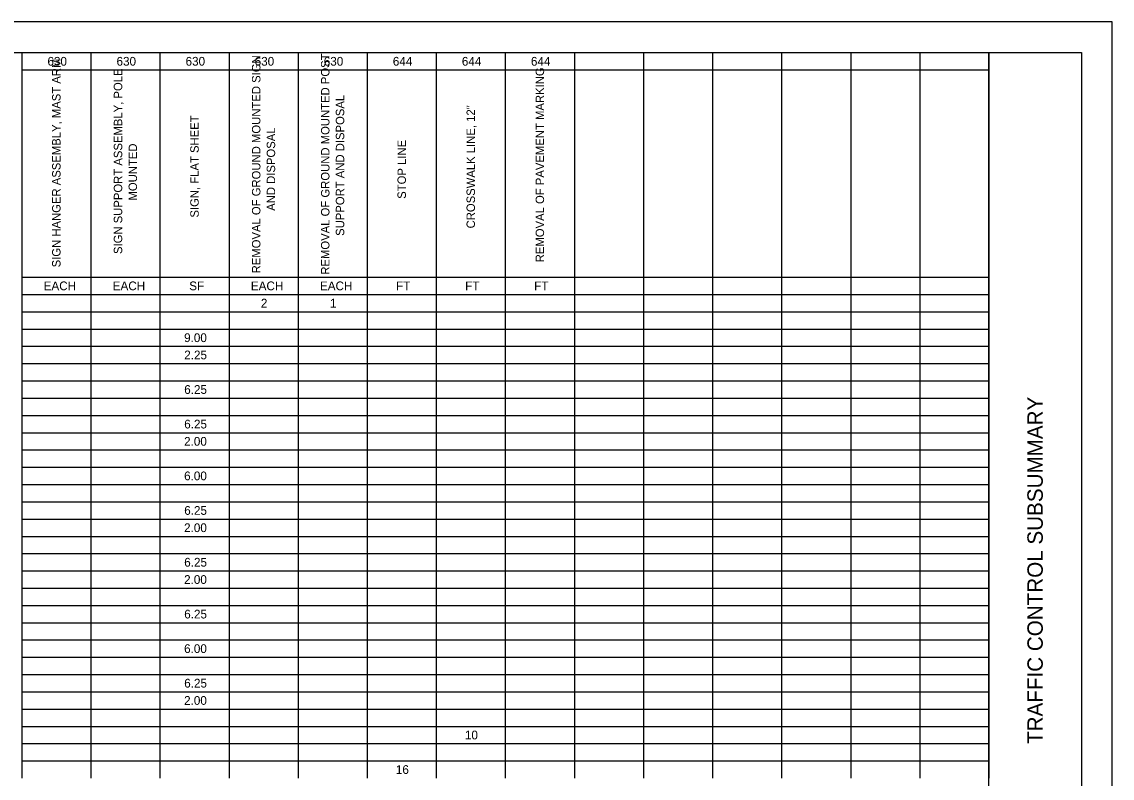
# Model space of a CAD drawing. Extents: x 0 to 34, y 0 to 22.
# Drawn here: x 16.33 to 34, y 9.74 to 22 of the extents above; entities that cross this region are included whole.
import ezdxf

# ---------------------------------------------------------------- set-up
doc = ezdxf.new("R2010")
doc.units = 0
for name, color, linetype in [('SH_Border', 7, 'Continuous'), ('SH_Cut_Line', 7, 'Continuous'), ('SH_Data', 7, 'Continuous')]:
    doc.layers.add(name, color=color, linetype=linetype)

msp = doc.modelspace()

# ---------------------------------------------------------------- linework, layer by layer
at = {"layer": 'SH_Border'}
msp.add_line((32, 0.5), (32, 21.5), dxfattribs=at)
msp.add_lwpolyline([(1.5, 21.5), (33.5, 21.5), (33.5, 0.5), (1.5, 0.5)], close=True, dxfattribs=at)
at = {"layer": 'SH_Cut_Line'}
msp.add_lwpolyline([(0, 0), (34, 0), (34, 22), (0, 22)], close=True, dxfattribs=at)
at = {"layer": 'SH_Data'}
for p, q in [((16.325, 21.5), (24.163, 21.5)), ((16.325, 21.5), (16.325, 21.22)), ((17.445, 21.5), (17.445, 21.22)), ((18.565, 21.5), (18.565, 21.22)), ((19.684, 21.5), (19.684, 21.22)), ((20.804, 21.5), (20.804, 21.22)), ((21.923, 21.5), (21.923, 21.22)), ((23.043, 21.5), (23.043, 21.22)), ((24.163, 21.5), (25.282, 21.5)), ((24.163, 21.5), (24.163, 21.22)), ((25.282, 21.5), (27.522, 21.5)), ((25.282, 21.5), (25.282, 21.22)), ((26.402, 21.5), (26.402, 21.22)), ((27.522, 21.5), (30.88, 21.5)), ((27.522, 21.5), (27.522, 21.22)), ((28.641, 21.5), (28.641, 21.22)), ((29.761, 21.5), (29.761, 21.22)), ((30.88, 21.5), (32, 21.5)), ((30.88, 21.5), (30.88, 21.22)), ((32, 21.5), (32, 21.22)), ((16.325, 21.22), (24.163, 21.22)), ((16.325, 21.22), (16.325, 20.94)), ((17.445, 21.22), (17.445, 20.94)), ((18.565, 21.22), (18.565, 20.94)), ((19.684, 21.22), (19.684, 20.94)), ((20.804, 21.22), (20.804, 20.94)), ((21.923, 21.22), (21.923, 20.94)), ((23.043, 21.22), (23.043, 20.94)), ((24.163, 21.22), (25.282, 21.22)), ((24.163, 21.22), (24.163, 20.94)), ((25.282, 21.22), (27.522, 21.22)), ((25.282, 21.22), (25.282, 20.94)), ((26.402, 21.22), (26.402, 20.94)), ((27.522, 21.22), (30.88, 21.22)), ((27.522, 21.22), (27.522, 20.94)), ((28.641, 21.22), (28.641, 20.94)), ((29.761, 21.22), (29.761, 20.94)), ((30.88, 21.22), (32, 21.22)), ((30.88, 21.22), (30.88, 20.94)), ((32, 21.22), (32, 20.94)), ((16.325, 20.94), (16.325, 20.66)), ((17.445, 20.94), (17.445, 20.66)), ((18.565, 20.94), (18.565, 20.66)), ((19.684, 20.94), (19.684, 20.66)), ((20.804, 20.94), (20.804, 20.66)), ((21.923, 20.94), (21.923, 20.66)), ((23.043, 20.94), (23.043, 20.66)), ((24.163, 20.94), (24.163, 20.66)), ((25.282, 20.94), (25.282, 20.66)), ((26.402, 20.94), (26.402, 20.66)), ((27.522, 20.94), (27.522, 20.66)), ((28.641, 20.94), (28.641, 20.66)), ((29.761, 20.94), (29.761, 20.66)), ((30.88, 20.94), (30.88, 20.66)), ((32, 20.94), (32, 20.66)), ((16.325, 20.66), (16.325, 20.38)), ((17.445, 20.66), (17.445, 20.38)), ((18.565, 20.66), (18.565, 20.38)), ((19.684, 20.66), (19.684, 20.38)), ((20.804, 20.66), (20.804, 20.38)), ((21.923, 20.66), (21.923, 20.38)), ((23.043, 20.66), (23.043, 20.38)), ((24.163, 20.66), (24.163, 20.38)), ((25.282, 20.66), (25.282, 20.38)), ((26.402, 20.66), (26.402, 20.38)), ((27.522, 20.66), (27.522, 20.38)), ((28.641, 20.66), (28.641, 20.38)), ((29.761, 20.66), (29.761, 20.38)), ((30.88, 20.66), (30.88, 20.38)), ((32, 20.66), (32, 20.38)), ((16.325, 20.38), (16.325, 20.1)), ((17.445, 20.38), (17.445, 20.1)), ((18.565, 20.38), (18.565, 20.1)), ((19.684, 20.38), (19.684, 20.1)), ((20.804, 20.38), (20.804, 20.1)), ((21.923, 20.38), (21.923, 20.1)), ((23.043, 20.38), (23.043, 20.1)), ((24.163, 20.38), (24.163, 20.1)), ((25.282, 20.38), (25.282, 20.1)), ((26.402, 20.38), (26.402, 20.1)), ((27.522, 20.38), (27.522, 20.1)), ((28.641, 20.38), (28.641, 20.1)), ((29.761, 20.38), (29.761, 20.1)), ((30.88, 20.38), (30.88, 20.1)), ((32, 20.38), (32, 20.1)), ((16.325, 20.1), (16.325, 19.82)), ((17.445, 20.1), (17.445, 19.82)), ((18.565, 20.1), (18.565, 19.82)), ((19.684, 20.1), (19.684, 19.82)), ((20.804, 20.1), (20.804, 19.82)), ((21.923, 20.1), (21.923, 19.82)), ((23.043, 20.1), (23.043, 19.82)), ((24.163, 20.1), (24.163, 19.82)), ((25.282, 20.1), (25.282, 19.82)), ((26.402, 20.1), (26.402, 19.82)), ((27.522, 20.1), (27.522, 19.82)), ((28.641, 20.1), (28.641, 19.82)), ((29.761, 20.1), (29.761, 19.82)), ((30.88, 20.1), (30.88, 19.82)), ((32, 20.1), (32, 19.82)), ((16.325, 19.82), (16.325, 19.54)), ((17.445, 19.82), (17.445, 19.54)), ((18.565, 19.82), (18.565, 19.54)), ((19.684, 19.82), (19.684, 19.54)), ((20.804, 19.82), (20.804, 19.54)), ((21.923, 19.82), (21.923, 19.54)), ((23.043, 19.82), (23.043, 19.54)), ((24.163, 19.82), (24.163, 19.54)), ((25.282, 19.82), (25.282, 19.54)), ((26.402, 19.82), (26.402, 19.54)), ((27.522, 19.82), (27.522, 19.54)), ((28.641, 19.82), (28.641, 19.54)), ((29.761, 19.82), (29.761, 19.54)), ((30.88, 19.82), (30.88, 19.54)), ((32, 19.82), (32, 19.54)), ((16.325, 19.54), (16.325, 18.98)), ((17.445, 19.54), (17.445, 18.98)), ((18.565, 19.54), (18.565, 18.98)), ((19.684, 19.54), (19.684, 18.98)), ((20.804, 19.54), (20.804, 18.98)), ((21.923, 19.54), (21.923, 18.98)), ((23.043, 19.54), (23.043, 18.98)), ((24.163, 19.54), (24.163, 18.98)), ((25.282, 19.54), (25.282, 18.98)), ((26.402, 19.54), (26.402, 18.98)), ((27.522, 19.54), (27.522, 18.98)), ((28.641, 19.54), (28.641, 18.98)), ((29.761, 19.54), (29.761, 18.98)), ((30.88, 19.54), (30.88, 18.98)), ((32, 19.54), (32, 18.98)), ((16.325, 18.98), (16.325, 18.14)), ((17.445, 18.98), (17.445, 18.14)), ((18.565, 18.98), (18.565, 18.14)), ((19.684, 18.98), (19.684, 18.14)), ((20.804, 18.98), (20.804, 18.14)), ((21.923, 18.98), (21.923, 18.14)), ((23.043, 18.98), (23.043, 18.14)), ((24.163, 18.98), (24.163, 18.14)), ((25.282, 18.98), (25.282, 18.14)), ((26.402, 18.98), (26.402, 18.14)), ((27.522, 18.98), (27.522, 18.14)), ((28.641, 18.98), (28.641, 18.14)), ((29.761, 18.98), (29.761, 18.14)), ((30.88, 18.98), (30.88, 18.14)), ((32, 18.98), (32, 18.14)), ((16.325, 18.14), (16.325, 17.86)), ((17.445, 18.14), (17.445, 17.86)), ((18.565, 18.14), (18.565, 17.86)), ((19.684, 18.14), (19.684, 17.86)), ((20.804, 18.14), (20.804, 17.86)), ((21.923, 18.14), (21.923, 17.86)), ((23.043, 18.14), (23.043, 17.86)), ((24.163, 18.14), (24.163, 17.86)), ((25.282, 18.14), (25.282, 17.86)), ((26.402, 18.14), (26.402, 17.86)), ((27.522, 18.14), (27.522, 17.86)), ((28.641, 18.14), (28.641, 17.86)), ((29.761, 18.14), (29.761, 17.86)), ((30.88, 18.14), (30.88, 17.86)), ((32, 18.14), (32, 17.86)), ((16.325, 17.86), (24.163, 17.86)), ((16.325, 17.86), (16.325, 17.3)), ((17.445, 17.86), (17.445, 17.3)), ((18.565, 17.86), (18.565, 17.3)), ((19.684, 17.86), (19.684, 17.3)), ((20.804, 17.86), (20.804, 17.3)), ((21.923, 17.86), (21.923, 17.3)), ((23.043, 17.86), (23.043, 17.3)), ((24.163, 17.86), (25.282, 17.86)), ((24.163, 17.86), (24.163, 17.3)), ((25.282, 17.86), (27.522, 17.86)), ((25.282, 17.86), (25.282, 17.3)), ((26.402, 17.86), (26.402, 17.3)), ((27.522, 17.86), (30.88, 17.86)), ((27.522, 17.86), (27.522, 17.3)), ((28.641, 17.86), (28.641, 17.3)), ((29.761, 17.86), (29.761, 17.3)), ((30.88, 17.86), (32, 17.86)), ((30.88, 17.86), (30.88, 17.3)), ((32, 17.86), (32, 17.3)), ((16.325, 17.58), (24.163, 17.58)), ((24.163, 17.58), (25.282, 17.58)), ((25.282, 17.58), (27.522, 17.58)), ((27.522, 17.58), (30.88, 17.58)), ((30.88, 17.58), (32, 17.58)), ((16.325, 17.3), (24.163, 17.3)), ((16.325, 17.3), (16.325, 17.02)), ((17.445, 17.3), (17.445, 17.02)), ((18.565, 17.3), (18.565, 17.02)), ((19.684, 17.3), (19.684, 17.02)), ((20.804, 17.3), (20.804, 17.02)), ((21.923, 17.3), (21.923, 17.02)), ((23.043, 17.3), (23.043, 17.02)), ((24.163, 17.3), (25.282, 17.3)), ((24.163, 17.3), (24.163, 17.02)), ((25.282, 17.3), (27.522, 17.3)), ((25.282, 17.3), (25.282, 17.02)), ((26.402, 17.3), (26.402, 17.02)), ((27.522, 17.3), (30.88, 17.3)), ((27.522, 17.3), (27.522, 17.02)), ((28.641, 17.3), (28.641, 17.02)), ((29.761, 17.3), (29.761, 17.02)), ((30.88, 17.3), (32, 17.3)), ((30.88, 17.3), (30.88, 17.02)), ((32, 17.3), (32, 17.02)), ((16.325, 17.02), (24.163, 17.02)), ((16.325, 17.02), (16.325, 15.9)), ((17.445, 17.02), (17.445, 15.9)), ((18.565, 17.02), (18.565, 15.9)), ((19.684, 17.02), (19.684, 15.9)), ((20.804, 17.02), (20.804, 15.9)), ((21.923, 17.02), (21.923, 15.9)), ((23.043, 17.02), (23.043, 15.9)), ((24.163, 17.02), (25.282, 17.02)), ((24.163, 17.02), (24.163, 15.9)), ((25.282, 17.02), (27.522, 17.02)), ((25.282, 17.02), (25.282, 15.9)), ((26.402, 17.02), (26.402, 15.9)), ((27.522, 17.02), (30.88, 17.02)), ((27.522, 17.02), (27.522, 15.9)), ((28.641, 17.02), (28.641, 15.9)), ((29.761, 17.02), (29.761, 15.9)), ((30.88, 17.02), (32, 17.02)), ((30.88, 17.02), (30.88, 15.9)), ((32, 17.02), (32, 15.9)), ((16.325, 16.74), (24.163, 16.74)), ((24.163, 16.74), (25.282, 16.74)), ((25.282, 16.74), (27.522, 16.74)), ((27.522, 16.74), (30.88, 16.74)), ((30.88, 16.74), (32, 16.74)), ((16.325, 16.46), (24.163, 16.46)), ((24.163, 16.46), (25.282, 16.46)), ((25.282, 16.46), (27.522, 16.46)), ((27.522, 16.46), (30.88, 16.46)), ((30.88, 16.46), (32, 16.46)), ((16.325, 16.18), (24.163, 16.18)), ((24.163, 16.18), (25.282, 16.18)), ((25.282, 16.18), (27.522, 16.18)), ((27.522, 16.18), (30.88, 16.18)), ((30.88, 16.18), (32, 16.18)), ((16.325, 15.9), (24.163, 15.9)), ((16.325, 15.9), (16.325, 15.62)), ((17.445, 15.9), (17.445, 15.62)), ((18.565, 15.9), (18.565, 15.62)), ((19.684, 15.9), (19.684, 15.62)), ((20.804, 15.9), (20.804, 15.62)), ((21.923, 15.9), (21.923, 15.62)), ((23.043, 15.9), (23.043, 15.62)), ((24.163, 15.9), (25.282, 15.9)), ((24.163, 15.9), (24.163, 15.62)), ((25.282, 15.9), (27.522, 15.9)), ((25.282, 15.9), (25.282, 15.62)), ((26.402, 15.9), (26.402, 15.62)), ((27.522, 15.9), (30.88, 15.9)), ((27.522, 15.9), (27.522, 15.62)), ((28.641, 15.9), (28.641, 15.62)), ((29.761, 15.9), (29.761, 15.62)), ((30.88, 15.9), (32, 15.9)), ((30.88, 15.9), (30.88, 15.62)), ((32, 15.9), (32, 15.62)), ((16.325, 15.62), (24.163, 15.62)), ((16.325, 15.62), (16.325, 15.06)), ((17.445, 15.62), (17.445, 15.06)), ((18.565, 15.62), (18.565, 15.06)), ((19.684, 15.62), (19.684, 15.06)), ((20.804, 15.62), (20.804, 15.06)), ((21.923, 15.62), (21.923, 15.06)), ((23.043, 15.62), (23.043, 15.06)), ((24.163, 15.62), (25.282, 15.62)), ((24.163, 15.62), (24.163, 15.06)), ((25.282, 15.62), (27.522, 15.62)), ((25.282, 15.62), (25.282, 15.06)), ((26.402, 15.62), (26.402, 15.06)), ((27.522, 15.62), (30.88, 15.62)), ((27.522, 15.62), (27.522, 15.06)), ((28.641, 15.62), (28.641, 15.06)), ((29.761, 15.62), (29.761, 15.06)), ((30.88, 15.62), (32, 15.62)), ((30.88, 15.62), (30.88, 15.06)), ((32, 15.62), (32, 15.06)), ((16.325, 15.34), (24.163, 15.34)), ((24.163, 15.34), (25.282, 15.34)), ((25.282, 15.34), (27.522, 15.34)), ((27.522, 15.34), (30.88, 15.34)), ((30.88, 15.34), (32, 15.34)), ((16.325, 15.06), (24.163, 15.06)), ((16.325, 15.06), (16.325, 14.5)), ((17.445, 15.06), (17.445, 14.5)), ((18.565, 15.06), (18.565, 14.5)), ((19.684, 15.06), (19.684, 14.5)), ((20.804, 15.06), (20.804, 14.5)), ((21.923, 15.06), (21.923, 14.5)), ((23.043, 15.06), (23.043, 14.5)), ((24.163, 15.06), (25.282, 15.06)), ((24.163, 15.06), (24.163, 14.5)), ((25.282, 15.06), (27.522, 15.06)), ((25.282, 15.06), (25.282, 14.5)), ((26.402, 15.06), (26.402, 14.5)), ((27.522, 15.06), (30.88, 15.06)), ((27.522, 15.06), (27.522, 14.5)), ((28.641, 15.06), (28.641, 14.5)), ((29.761, 15.06), (29.761, 14.5)), ((30.88, 15.06), (32, 15.06)), ((30.88, 15.06), (30.88, 14.5)), ((32, 15.06), (32, 14.5)), ((16.325, 14.78), (24.163, 14.78)), ((24.163, 14.78), (25.282, 14.78)), ((25.282, 14.78), (27.522, 14.78)), ((27.522, 14.78), (30.88, 14.78)), ((30.88, 14.78), (32, 14.78)), ((16.325, 14.5), (24.163, 14.5)), ((16.325, 14.5), (16.325, 14.22)), ((17.445, 14.5), (17.445, 14.22)), ((18.565, 14.5), (18.565, 14.22)), ((19.684, 14.5), (19.684, 14.22)), ((20.804, 14.5), (20.804, 14.22)), ((21.923, 14.5), (21.923, 14.22)), ((23.043, 14.5), (23.043, 14.22)), ((24.163, 14.5), (25.282, 14.5)), ((24.163, 14.5), (24.163, 14.22)), ((25.282, 14.5), (27.522, 14.5)), ((25.282, 14.5), (25.282, 14.22)), ((26.402, 14.5), (26.402, 14.22)), ((27.522, 14.5), (30.88, 14.5)), ((27.522, 14.5), (27.522, 14.22)), ((28.641, 14.5), (28.641, 14.22)), ((29.761, 14.5), (29.761, 14.22)), ((30.88, 14.5), (32, 14.5)), ((30.88, 14.5), (30.88, 14.22)), ((32, 14.5), (32, 14.22)), ((16.325, 14.22), (24.163, 14.22)), ((16.325, 14.22), (16.325, 13.66)), ((17.445, 14.22), (17.445, 13.66)), ((18.565, 14.22), (18.565, 13.66)), ((19.684, 14.22), (19.684, 13.66)), ((20.804, 14.22), (20.804, 13.66)), ((21.923, 14.22), (21.923, 13.66)), ((23.043, 14.22), (23.043, 13.66)), ((24.163, 14.22), (25.282, 14.22)), ((24.163, 14.22), (24.163, 13.66)), ((25.282, 14.22), (27.522, 14.22)), ((25.282, 14.22), (25.282, 13.66)), ((26.402, 14.22), (26.402, 13.66)), ((27.522, 14.22), (30.88, 14.22)), ((27.522, 14.22), (27.522, 13.66)), ((28.641, 14.22), (28.641, 13.66)), ((29.761, 14.22), (29.761, 13.66)), ((30.88, 14.22), (32, 14.22)), ((30.88, 14.22), (30.88, 13.66)), ((32, 14.22), (32, 13.66)), ((16.325, 13.94), (24.163, 13.94)), ((24.163, 13.94), (25.282, 13.94)), ((25.282, 13.94), (27.522, 13.94)), ((27.522, 13.94), (30.88, 13.94)), ((30.88, 13.94), (32, 13.94)), ((16.325, 13.66), (24.163, 13.66)), ((16.325, 13.66), (16.325, 13.38)), ((17.445, 13.66), (17.445, 13.38)), ((18.565, 13.66), (18.565, 13.38)), ((19.684, 13.66), (19.684, 13.38)), ((20.804, 13.66), (20.804, 13.38)), ((21.923, 13.66), (21.923, 13.38)), ((23.043, 13.66), (23.043, 13.38)), ((24.163, 13.66), (25.282, 13.66)), ((24.163, 13.66), (24.163, 13.38)), ((25.282, 13.66), (27.522, 13.66)), ((25.282, 13.66), (25.282, 13.38)), ((26.402, 13.66), (26.402, 13.38)), ((27.522, 13.66), (30.88, 13.66)), ((27.522, 13.66), (27.522, 13.38)), ((28.641, 13.66), (28.641, 13.38)), ((29.761, 13.66), (29.761, 13.38)), ((30.88, 13.66), (32, 13.66)), ((30.88, 13.66), (30.88, 13.38)), ((32, 13.66), (32, 13.38)), ((16.325, 13.38), (24.163, 13.38)), ((16.325, 13.38), (16.325, 12.54)), ((17.445, 13.38), (17.445, 12.54)), ((18.565, 13.38), (18.565, 12.54)), ((19.684, 13.38), (19.684, 12.54)), ((20.804, 13.38), (20.804, 12.54)), ((21.923, 13.38), (21.923, 12.54)), ((23.043, 13.38), (23.043, 12.54)), ((24.163, 13.38), (25.282, 13.38)), ((24.163, 13.38), (24.163, 12.54)), ((25.282, 13.38), (27.522, 13.38)), ((25.282, 13.38), (25.282, 12.54)), ((26.402, 13.38), (26.402, 12.54)), ((27.522, 13.38), (30.88, 13.38)), ((27.522, 13.38), (27.522, 12.54)), ((28.641, 13.38), (28.641, 12.54)), ((29.761, 13.38), (29.761, 12.54)), ((30.88, 13.38), (32, 13.38)), ((30.88, 13.38), (30.88, 12.54)), ((32, 13.38), (32, 12.54)), ((16.325, 13.1), (24.163, 13.1)), ((24.163, 13.1), (25.282, 13.1)), ((25.282, 13.1), (27.522, 13.1)), ((27.522, 13.1), (30.88, 13.1)), ((30.88, 13.1), (32, 13.1)), ((16.325, 12.82), (24.163, 12.82)), ((24.163, 12.82), (25.282, 12.82)), ((25.282, 12.82), (27.522, 12.82)), ((27.522, 12.82), (30.88, 12.82)), ((30.88, 12.82), (32, 12.82)), ((16.325, 12.54), (24.163, 12.54)), ((16.325, 12.54), (16.325, 11.98)), ((17.445, 12.54), (17.445, 11.98)), ((18.565, 12.54), (18.565, 11.98)), ((19.684, 12.54), (19.684, 11.98)), ((20.804, 12.54), (20.804, 11.98)), ((21.923, 12.54), (21.923, 11.98)), ((23.043, 12.54), (23.043, 11.98)), ((24.163, 12.54), (25.282, 12.54)), ((24.163, 12.54), (24.163, 11.98)), ((25.282, 12.54), (27.522, 12.54)), ((25.282, 12.54), (25.282, 11.98)), ((26.402, 12.54), (26.402, 11.98)), ((27.522, 12.54), (30.88, 12.54)), ((27.522, 12.54), (27.522, 11.98)), ((28.641, 12.54), (28.641, 11.98)), ((29.761, 12.54), (29.761, 11.98)), ((30.88, 12.54), (32, 12.54)), ((30.88, 12.54), (30.88, 11.98)), ((32, 12.54), (32, 11.98)), ((16.325, 12.26), (24.163, 12.26)), ((24.163, 12.26), (25.282, 12.26)), ((25.282, 12.26), (27.522, 12.26)), ((27.522, 12.26), (30.88, 12.26)), ((30.88, 12.26), (32, 12.26)), ((16.325, 11.98), (24.163, 11.98)), ((16.325, 11.98), (16.325, 11.14)), ((17.445, 11.98), (17.445, 11.14)), ((18.565, 11.98), (18.565, 11.14)), ((19.684, 11.98), (19.684, 11.14)), ((20.804, 11.98), (20.804, 11.14)), ((21.923, 11.98), (21.923, 11.14)), ((23.043, 11.98), (23.043, 11.14)), ((24.163, 11.98), (25.282, 11.98)), ((24.163, 11.98), (24.163, 11.14)), ((25.282, 11.98), (27.522, 11.98)), ((25.282, 11.98), (25.282, 11.14)), ((26.402, 11.98), (26.402, 11.14)), ((27.522, 11.98), (30.88, 11.98)), ((27.522, 11.98), (27.522, 11.14)), ((28.641, 11.98), (28.641, 11.14)), ((29.761, 11.98), (29.761, 11.14)), ((30.88, 11.98), (32, 11.98)), ((30.88, 11.98), (30.88, 11.14)), ((32, 11.98), (32, 11.14)), ((16.325, 11.7), (24.163, 11.7)), ((24.163, 11.7), (25.282, 11.7)), ((25.282, 11.7), (27.522, 11.7)), ((27.522, 11.7), (30.88, 11.7)), ((30.88, 11.7), (32, 11.7)), ((16.325, 11.42), (24.163, 11.42)), ((24.163, 11.42), (25.282, 11.42)), ((25.282, 11.42), (27.522, 11.42)), ((27.522, 11.42), (30.88, 11.42)), ((30.88, 11.42), (32, 11.42)), ((16.325, 11.14), (24.163, 11.14)), ((16.325, 11.14), (16.325, 10.58)), ((17.445, 11.14), (17.445, 10.58)), ((18.565, 11.14), (18.565, 10.58)), ((19.684, 11.14), (19.684, 10.58)), ((20.804, 11.14), (20.804, 10.58)), ((21.923, 11.14), (21.923, 10.58)), ((23.043, 11.14), (23.043, 10.58)), ((24.163, 11.14), (25.282, 11.14)), ((24.163, 11.14), (24.163, 10.58)), ((25.282, 11.14), (27.522, 11.14)), ((25.282, 11.14), (25.282, 10.58)), ((26.402, 11.14), (26.402, 10.58)), ((27.522, 11.14), (30.88, 11.14)), ((27.522, 11.14), (27.522, 10.58)), ((28.641, 11.14), (28.641, 10.58)), ((29.761, 11.14), (29.761, 10.58)), ((30.88, 11.14), (32, 11.14)), ((30.88, 11.14), (30.88, 10.58)), ((32, 11.14), (32, 10.58)), ((16.325, 10.86), (24.163, 10.86)), ((24.163, 10.86), (25.282, 10.86)), ((25.282, 10.86), (27.522, 10.86)), ((27.522, 10.86), (30.88, 10.86)), ((30.88, 10.86), (32, 10.86)), ((16.325, 10.58), (24.163, 10.58)), ((16.325, 10.58), (16.325, 9.74)), ((17.445, 10.58), (17.445, 9.74)), ((18.565, 10.58), (18.565, 9.74)), ((19.684, 10.58), (19.684, 9.74)), ((20.804, 10.58), (20.804, 9.74)), ((21.923, 10.58), (21.923, 9.74)), ((23.043, 10.58), (23.043, 9.74)), ((24.163, 10.58), (25.282, 10.58)), ((24.163, 10.58), (24.163, 9.74)), ((25.282, 10.58), (27.522, 10.58)), ((25.282, 10.58), (25.282, 9.74)), ((26.402, 10.58), (26.402, 9.74)), ((27.522, 10.58), (30.88, 10.58)), ((27.522, 10.58), (27.522, 9.74)), ((28.641, 10.58), (28.641, 9.74)), ((29.761, 10.58), (29.761, 9.74)), ((30.88, 10.58), (32, 10.58)), ((30.88, 10.58), (30.88, 9.74)), ((32, 10.58), (32, 9.74)), ((16.325, 10.3), (24.163, 10.3)), ((24.163, 10.3), (25.282, 10.3)), ((25.282, 10.3), (27.522, 10.3)), ((27.522, 10.3), (30.88, 10.3)), ((30.88, 10.3), (32, 10.3)), ((16.325, 10.02), (24.163, 10.02)), ((24.163, 10.02), (25.282, 10.02)), ((25.282, 10.02), (27.522, 10.02)), ((27.522, 10.02), (30.88, 10.02)), ((30.88, 10.02), (32, 10.02))]:
    msp.add_line(p, q, dxfattribs=at)

# ---------------------------------------------------------------- texts
for s, height, p in [('630', 0.1417, (16.741, 21.289)), ('630', 0.1417, (17.861, 21.289)), ('630', 0.1417, (18.98, 21.289)), ('630', 0.1417, (20.1, 21.289)), ('630', 0.1417, (21.22, 21.289)), ('644', 0.1417, (22.339, 21.289)), ('644', 0.1417, (23.458, 21.289)), ('644', 0.1417, (24.578, 21.289)), ('EACH', 0.1417, (16.679, 17.649)), ('EACH', 0.1417, (17.799, 17.649)), ('SF', 0.1417, (19.039, 17.649)), ('EACH', 0.1417, (20.038, 17.649)), ('EACH', 0.1417, (21.158, 17.649)), ('FT', 0.1417, (22.392, 17.649)), ('FT', 0.1417, (23.512, 17.649)), ('FT', 0.1417, (24.631, 17.649)), ('2', 0.142, (20.2, 17.369)), ('1', 0.142, (21.32, 17.369)), ('9.00', 0.1417, (18.956, 16.809)), ('2.25', 0.1417, (18.958, 16.529)), ('6.25', 0.1417, (18.958, 15.969)), ('6.25', 0.1417, (18.958, 15.409)), ('2.00', 0.1417, (18.956, 15.129)), ('6.00', 0.1417, (18.956, 14.569)), ('6.25', 0.1417, (18.958, 14.009)), ('2.00', 0.1417, (18.956, 13.729)), ('6.25', 0.1417, (18.958, 13.169)), ('2.00', 0.1417, (18.956, 12.889)), ('6.25', 0.1417, (18.958, 12.329)), ('6.00', 0.1417, (18.956, 11.769)), ('6.25', 0.1417, (18.958, 11.209)), ('2.00', 0.1417, (18.956, 10.929)), ('10', 0.1417, (23.508, 10.369)), ('16', 0.1417, (22.389, 9.809))]:
    msp.add_text(s, height=height, dxfattribs=at).set_placement(p)
for s, height, p in [('SIGN HANGER ASSEMBLY, MAST ARM', 0.13674, (16.953, 18.02)), ('REMOVAL OF GROUND MOUNTED SIGN ', 0.13674, (20.193, 17.922)), ('REMOVAL OF GROUND MOUNTED POST ', 0.13674, (21.312, 17.901)), ('SIGN SUPPORT ASSEMBLY, POLE ', 0.13674, (17.953, 18.236)), ('REMOVAL OF PAVEMENT MARKING', 0.13674, (24.791, 18.102)), ('SUPPORT AND DISPOSAL', 0.13674, (21.552, 18.53)), ('CROSSWALK LINE, 12"', 0.13674, (23.671, 18.651)), ('SIGN, FLAT SHEET', 0.13674, (19.193, 18.827)), ('AND DISPOSAL', 0.13674, (20.432, 18.936)), ('MOUNTED', 0.1367, (18.193, 19.103)), ('STOP LINE', 0.1367, (22.552, 19.131)), ('TRAFFIC CONTROL SUBSUMMARY', 0.25, (32.875, 10.295))]:
    msp.add_text(s, height=height, rotation=90, dxfattribs=at).set_placement(p)

doc.saveas('drawing.dxf')
